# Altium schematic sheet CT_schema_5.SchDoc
size 512 x 457 mm
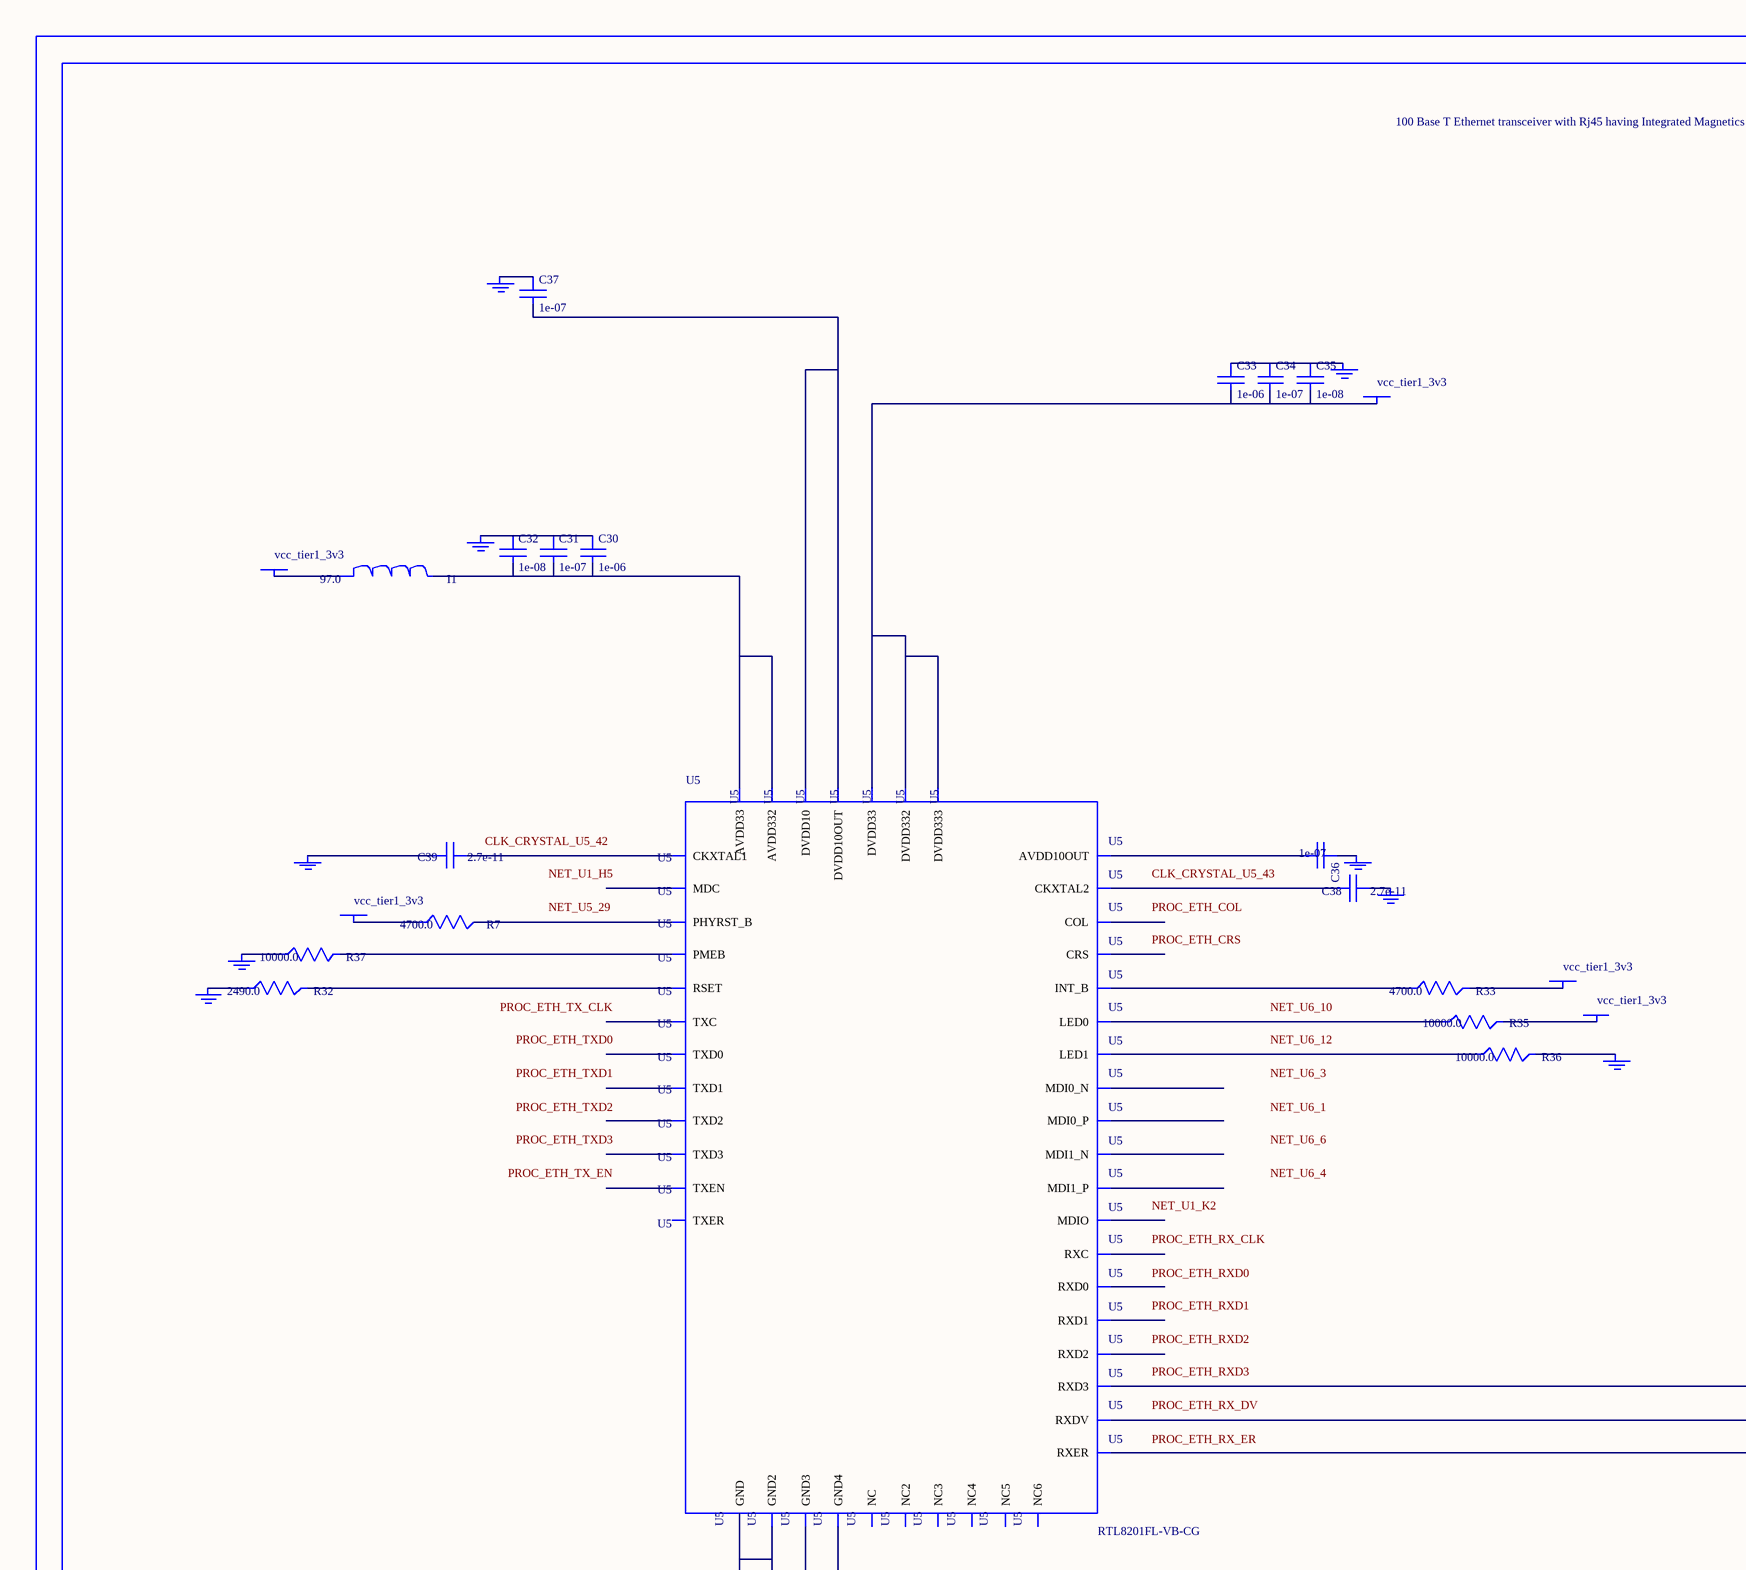
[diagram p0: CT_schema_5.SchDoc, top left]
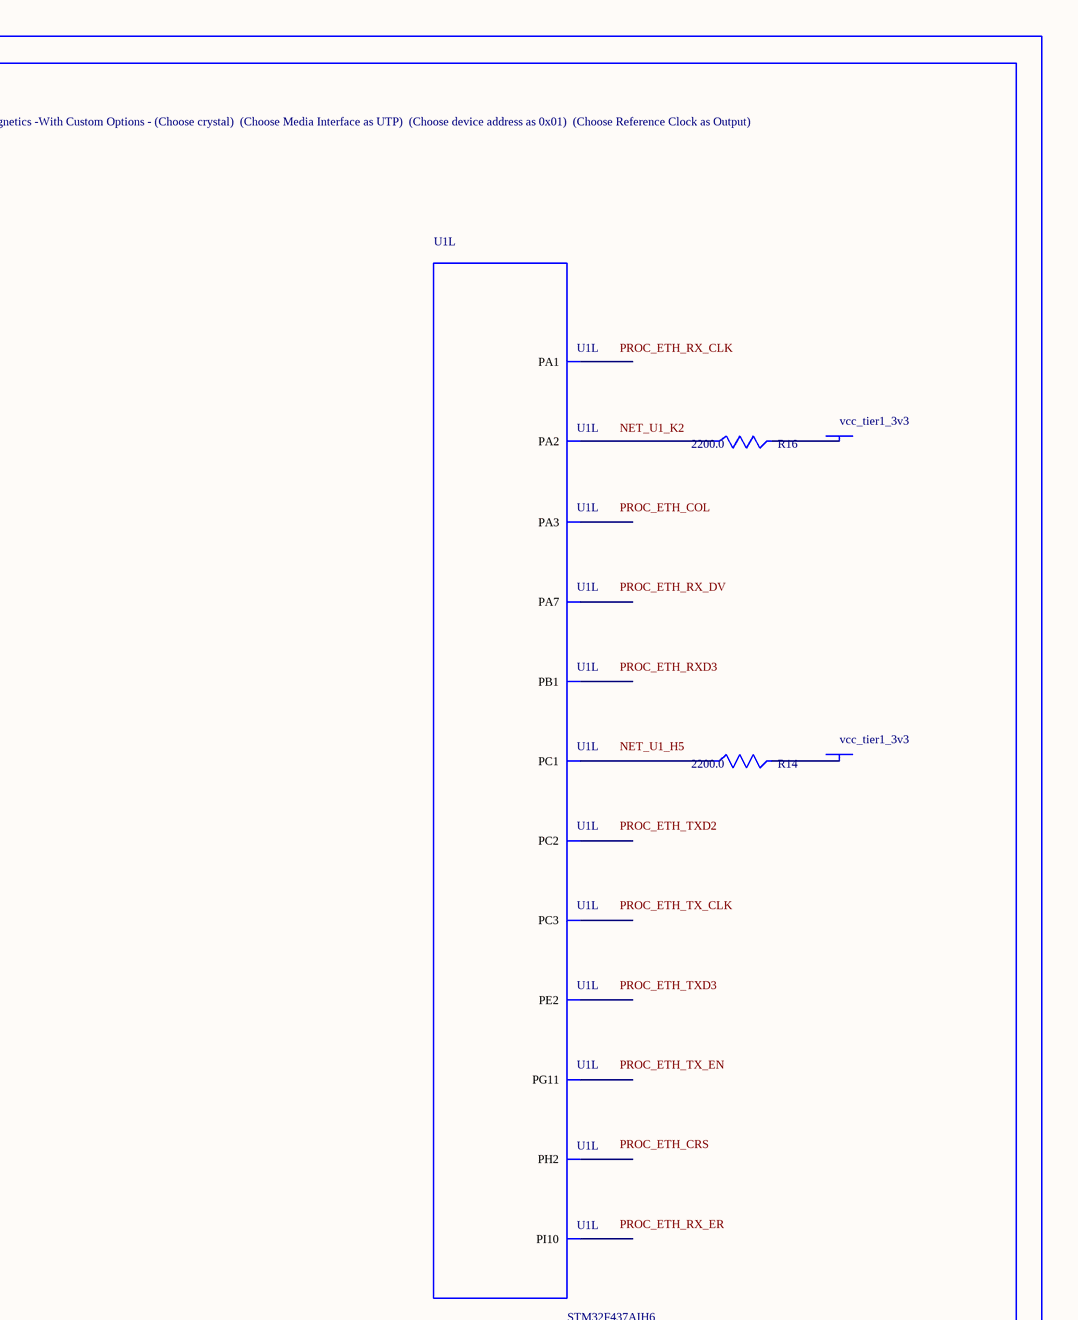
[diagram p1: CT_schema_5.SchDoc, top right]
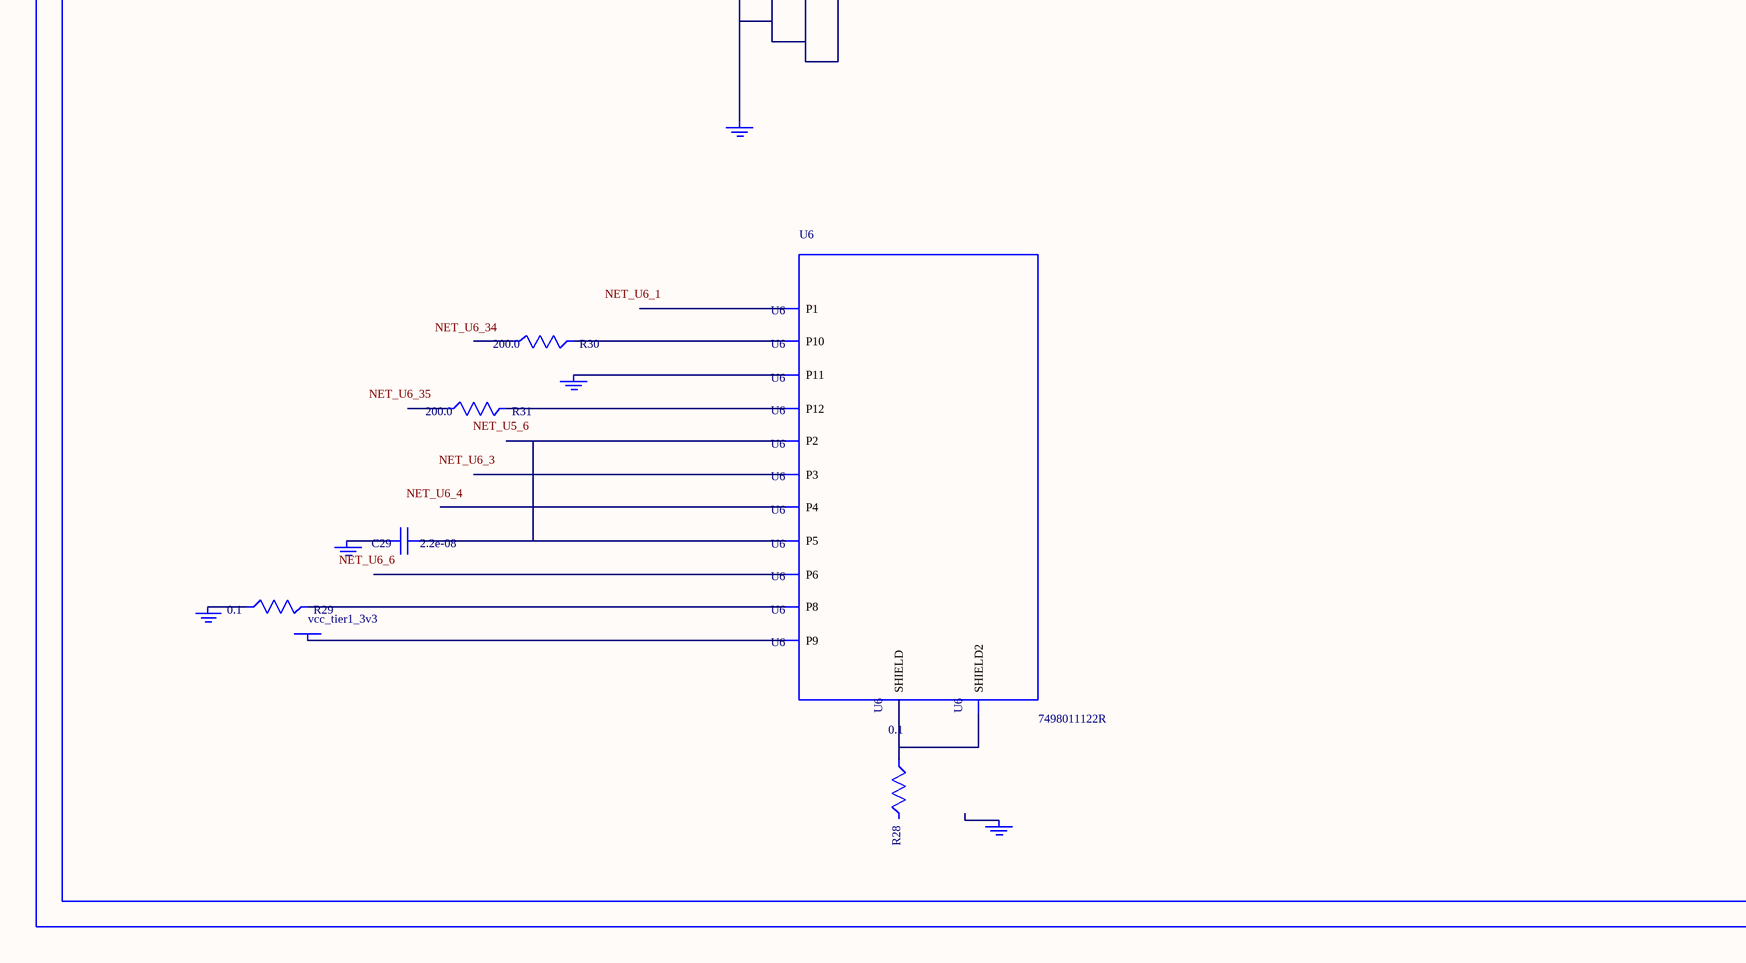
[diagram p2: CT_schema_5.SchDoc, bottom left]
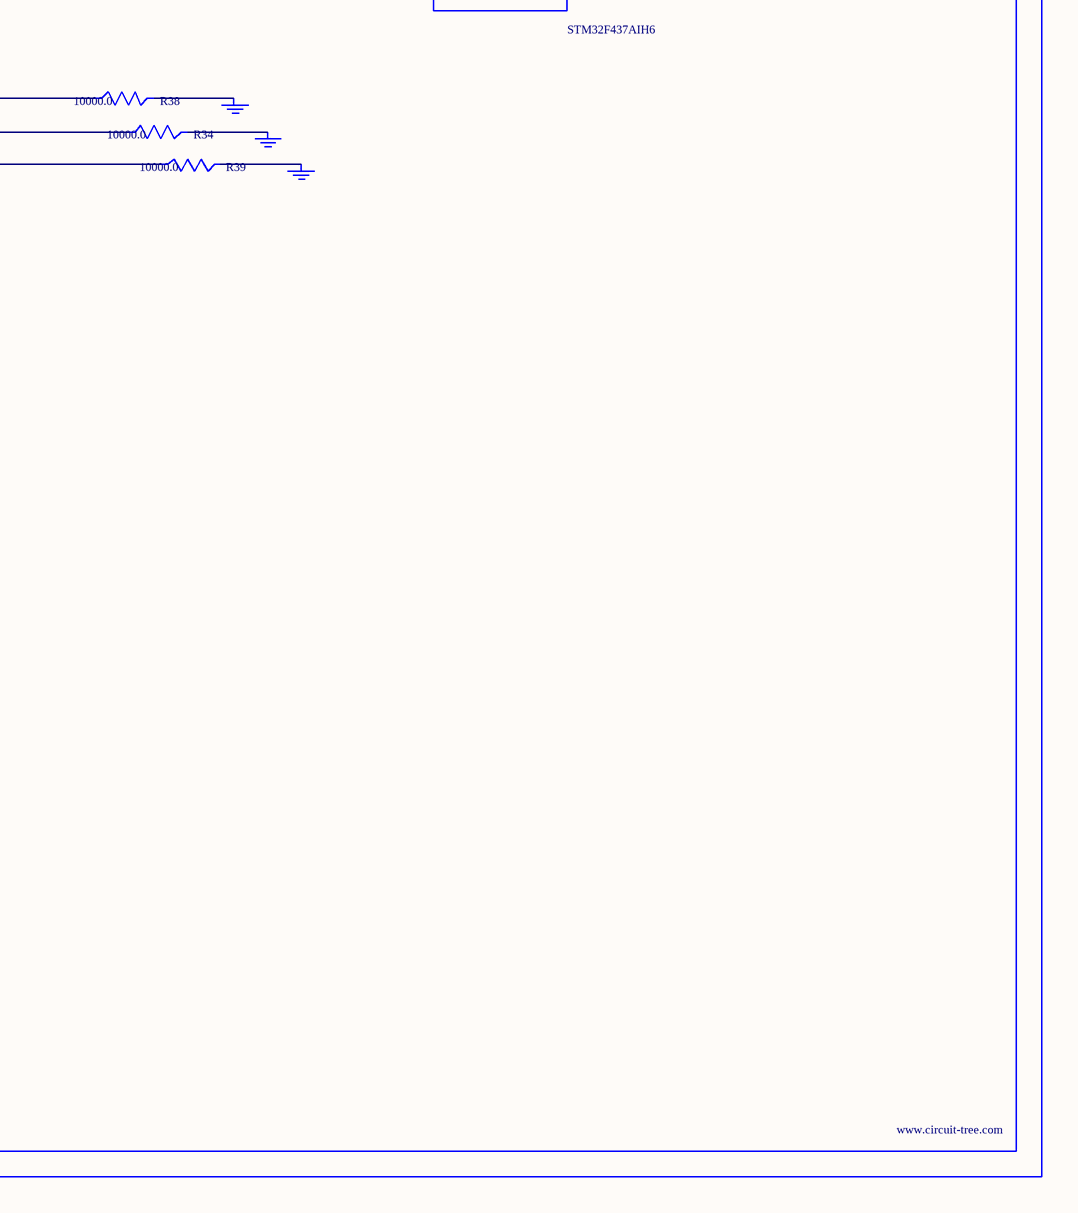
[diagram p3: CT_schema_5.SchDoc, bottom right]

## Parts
BORDER4  (no value)
C29  2.2e-08  [C0402]
C30  1e-06  [C0603]
C31  1e-07  [C0402]
C32  1e-08  [C0402]
C33  1e-06  [C0603]
C34  1e-07  [C0402]
C35  1e-08  [C0402]
C36  1e-07  [C0402]
C37  1e-07  [C0402]
C38  2.7e-11  [C0402]
C39  2.7e-11  [C0402]
GND_INSTANCE_4_0  (no value)
GND_INSTANCE_4_1  (no value)
GND_INSTANCE_4_2  (no value)
GND_INSTANCE_4_3  (no value)
GND_INSTANCE_4_4  (no value)
GND_INSTANCE_4_5  (no value)
GND_INSTANCE_4_6  (no value)
GND_INSTANCE_4_7  (no value)
GND_INSTANCE_4_8  (no value)
GND_INSTANCE_4_9  (no value)
GND_INSTANCE_4_10  (no value)
GND_INSTANCE_4_11  (no value)
GND_INSTANCE_4_12  (no value)
GND_INSTANCE_4_13  (no value)
GND_INSTANCE_4_14  (no value)
GND_INSTANCE_4_15  (no value)
GND_INSTANCE_4_16  (no value)
I1  97.0  [R0603]
POWER_INSTANCE_4_0  vcc_tier1_3v3
POWER_INSTANCE_4_1  vcc_tier1_3v3
POWER_INSTANCE_4_2  vcc_tier1_3v3
POWER_INSTANCE_4_3  vcc_tier1_3v3
POWER_INSTANCE_4_4  vcc_tier1_3v3
POWER_INSTANCE_4_5  vcc_tier1_3v3
POWER_INSTANCE_4_6  vcc_tier1_3v3
POWER_INSTANCE_4_7  vcc_tier1_3v3
R7  4700.0  [R0603]
R14  2200.0  [R0603]
R16  2200.0  [R0603]
R28  0.1  [R0603]
R29  0.1  [R0603]
R30  200.0  [R0603]
R31  200.0  [R0603]
R32  2490.0  [R0603]
R33  4700.0  [R0603]
R34  10000.0  [R0603]
R35  10000.0  [R0603]
R36  10000.0  [R0603]
R37  10000.0  [R0603]
R38  10000.0  [R0603]
R39  10000.0  [R0603]
U1  STM32F437AIH6  [UFBGA169]  (part L of 12)
U5  RTL8201FL-VB-CG  [RTL8201FL-VB-CG]
U6  7498011122R  [7498011122R]

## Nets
NetC29_1: C29.1 U6.2(P2) U6.5(P5)
NetC29_2: C29.2 GND_INSTANCE_4_13.0(GND)
NetC30_1: C30.1 C31.1 C32.1 GND_INSTANCE_4_0.0(GND)
NetC30_2: C30.2 C31.2 C32.2 I1.2 U5.6(AVDD33) U5.41(AVDD332)
NetC33_1: C33.1 C34.1 C35.1 GND_INSTANCE_4_3.0(GND)
NetC33_2: C33.2 C34.2 C35.2 POWER_INSTANCE_4_1.0(PWR) U5.15(DVDD33) U5.21(DVDD332) U5.37(DVDD333)
NetC36_1: C36.1 GND_INSTANCE_4_11.0(GND)
NetC36_2: C36.2 U5.48(AVDD10OUT)
NetC37_1: C37.1 GND_INSTANCE_4_7.0(GND)
NetC37_2: C37.2 U5.28(DVDD10) U5.40(DVDD10OUT)
NetC38_1: C38.1 GND_INSTANCE_4_9.0(GND)
NetC38_2: C38.2 U5.43(CKXTAL2)
NetC39_1: C39.1 U5.42(CKXTAL1)
NetC39_2: C39.2 GND_INSTANCE_4_8.0(GND)
NetGND_INSTANCE_4_1_0: GND_INSTANCE_4_1.0(GND) R37.1
NetGND_INSTANCE_4_2_0: GND_INSTANCE_4_2.0(GND) R34.2
NetGND_INSTANCE_4_4_0: GND_INSTANCE_4_4.0(GND) R38.2
NetGND_INSTANCE_4_5_0: GND_INSTANCE_4_5.0(GND) R36.2
NetGND_INSTANCE_4_6_0: GND_INSTANCE_4_6.0(GND) R39.2
NetGND_INSTANCE_4_10_0: GND_INSTANCE_4_10.0(GND) R32.1
NetGND_INSTANCE_4_12_0: GND_INSTANCE_4_12.0(GND) U5.7(GND) U5.20(GND2) U5.33(GND3) U5.47(GND4)
NetGND_INSTANCE_4_14_0: GND_INSTANCE_4_14.0(GND) R29.1
NetGND_INSTANCE_4_15_0: GND_INSTANCE_4_15.0(GND) U6.11(P11)
NetI1_1: I1.1 POWER_INSTANCE_4_0.0(PWR)
NetPOWER_INSTANCE_4_2_0: POWER_INSTANCE_4_2.0(PWR) R33.2
NetPOWER_INSTANCE_4_3_0: POWER_INSTANCE_4_3.0(PWR) R35.2
NetPOWER_INSTANCE_4_4_0: POWER_INSTANCE_4_4.0(PWR) R7.1
NetPOWER_INSTANCE_4_5_0: POWER_INSTANCE_4_5.0(PWR) R16.2
NetPOWER_INSTANCE_4_6_0: POWER_INSTANCE_4_6.0(PWR) R14.2
NetPOWER_INSTANCE_4_7_0: POWER_INSTANCE_4_7.0(PWR) U6.9(P9)
NetR7_2: R7.2 U5.29(PHYRST_B)
NetR14_1: R14.1 U1.H5(PC1)
NetR16_1: R16.1 U1.K2(PA2)
NetR28_1: R28.1 U6.13(SHIELD) U6.14(SHIELD2)
NetR29_2: R29.2 U6.8(P8)
NetR30_2: R30.2 U6.10(P10)
NetR31_2: R31.2 U6.12(P12)
NetR32_2: R32.2 U5.46(RSET)
NetR33_1: R33.1 U5.32(INT_B)
NetR34_1: R34.1 U5.13(RXDV)
NetR35_1: R35.1 U5.34(LED0)
NetR36_1: R36.1 U5.35(LED1)
NetR37_2: R37.2 U5.10(PMEB)
NetR38_1: R38.1 U5.18(RXD3)
NetR39_1: R39.1 U5.39(RXER)

Not connected (* = marked no-connect by the designer): GND_INSTANCE_4_16 0(GND); R28 2; R30 1; R31 1; U1 B2(PE2) B7(PG11) E3(PI10) H6(PC2) H7(PC3) K1(PA1) K3(PA3) K4(PA7) K5(PB1) L2(PH2); U5 1(MDI0_P) 2(MDI0_N) 3(NC) 4(MDI1_P) 5(MDI1_N) 8(NC2) 9(NC3) 11(NC4) 12(TXER) 14(RXD0) 16(RXD1) 17(RXD2) 19(RXC) 22(TXC) 23(TXD0) 24(TXD1) 25(TXD2) 26(TXD3) 27(TXEN) 30(MDC) 31(MDIO) 36(CRS) 38(COL) 44(NC5) 45(NC6); U6 1(P1) 3(P3) 4(P4) 6(P6)

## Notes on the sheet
- Labels drawn without touching a wire or pin: CLK_CRYSTAL_U5_42, CLK_CRYSTAL_U5_43, NET_U1_H5, NET_U1_K2, NET_U5_6, NET_U5_29, NET_U6_1, NET_U6_3, NET_U6_4, NET_U6_6, NET_U6_10, NET_U6_12, NET_U6_34, NET_U6_35, PROC_ETH_COL, PROC_ETH_CRS, PROC_ETH_RX_CLK, PROC_ETH_RX_DV, PROC_ETH_RX_ER, PROC_ETH_RXD0, PROC_ETH_RXD1, PROC_ETH_RXD2, PROC_ETH_RXD3, PROC_ETH_TX_CLK, PROC_ETH_TX_EN, PROC_ETH_TXD0, PROC_ETH_TXD1, PROC_ETH_TXD2, PROC_ETH_TXD3

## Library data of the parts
BORDER4 = BORDER_PAGE4
C29 = C0402C223K3RAC
C30 C33 = C0603C105K3RACTU
C31 C34 C36 C37 = C0402C104K3RACTU
C32 C35 = C0402C103K3RAC
C38 C39 = C0402C270K3RAC
GND_INSTANCE_4_0-GND_INSTANCE_4_16 = GND
I1 = I1
POWER_INSTANCE_4_0-POWER_INSTANCE_4_7 = PWR
R7 R33 = RC0603JR-074K7L
R14 R16 = RC0603JR-072K2L
R28 R29 = ERJ-3RSFR10V
R30 R31 = RC0603JR-07200RL
R32 = ERA-3AED2490V
R34-R39 = RC0603JR-0710KL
